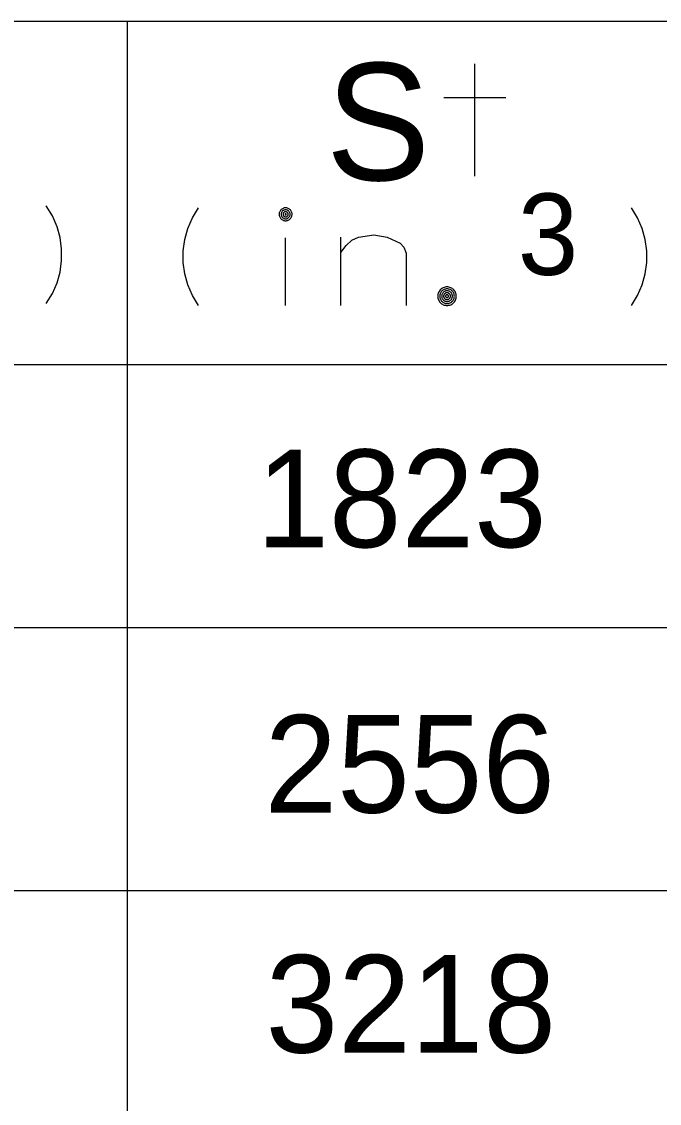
# Model space of a CAD drawing. Extents: x 635698 to 639877, y 296617 to 300175.
# Drawn here: x 639123.29 to 639142.89, y 299619.36 to 299652.6 of the extents above; entities that cross this region are included whole.
import ezdxf

# ---------------------------------------------------------------- set-up
doc = ezdxf.new("R2010")
doc.units = 0
for name, color, linetype in [('1', 7, 'Continuous'), ('2', 7, 'Continuous'), ('3', 7, 'Continuous')]:
    doc.layers.add(name, color=color, linetype=linetype)

msp = doc.modelspace()

# ---------------------------------------------------------------- linework, layer by layer
at = {"layer": '1'}
for p, q in [((639161.182, 299652.6), (639036.735, 299652.6)), ((639126.534, 299652.6), (639126.534, 299528.889)), ((639161.182, 299642.058), (639036.737, 299642.058)), ((639161.182, 299633.973), (639036.737, 299633.973)), ((639161.172, 299625.888), (639036.736, 299625.888)), ((639161.182, 299625.888), (639036.737, 299625.888))]:
    msp.add_line(p, q, dxfattribs=at)
at = {"layer": '2'}
for points in [[(639137.214, 299647.85), (639137.214, 299651.304)], [(639138.172, 299650.26), (639136.271, 299650.26)]]:
    msp.add_lwpolyline(points, dxfattribs=at)
at = {"layer": '3'}
for points in [[(639124.043, 299643.936), (639124.232, 299644.243), (639124.374, 299644.574), (639124.468, 299644.904), (639124.516, 299645.259), (639124.516, 299645.613), (639124.468, 299645.968), (639124.374, 299646.298), (639124.232, 299646.629), (639124.043, 299646.936)], [(639128.724, 299643.877), (639128.535, 299644.185), (639128.393, 299644.515), (639128.299, 299644.846), (639128.252, 299645.2), (639128.252, 299645.555), (639128.299, 299645.909), (639128.393, 299646.239), (639128.535, 299646.57), (639128.724, 299646.877)], [(639131.6, 299646.679), (639131.599, 299646.7), (639131.596, 299646.72), (639131.59, 299646.74), (639131.583, 299646.76), (639131.574, 299646.778), (639131.562, 299646.796), (639131.549, 299646.812), (639131.534, 299646.826), (639131.519, 299646.839), (639131.501, 299646.851), (639131.483, 299646.86), (639131.463, 299646.867), (639131.443, 299646.873), (639131.423, 299646.876), (639131.402, 299646.877), (639131.381, 299646.876), (639131.361, 299646.873), (639131.341, 299646.867), (639131.322, 299646.86), (639131.303, 299646.851), (639131.286, 299646.839), (639131.27, 299646.826), (639131.255, 299646.812), (639131.242, 299646.796), (639131.231, 299646.778), (639131.221, 299646.76), (639131.214, 299646.74), (639131.208, 299646.72), (639131.205, 299646.7), (639131.204, 299646.679), (639131.205, 299646.658), (639131.208, 299646.638), (639131.214, 299646.618), (639131.221, 299646.599), (639131.231, 299646.58), (639131.242, 299646.563), (639131.255, 299646.547), (639131.27, 299646.532), (639131.286, 299646.519), (639131.303, 299646.508), (639131.322, 299646.498), (639131.341, 299646.491), (639131.361, 299646.485), (639131.381, 299646.482), (639131.402, 299646.481), (639131.423, 299646.482), (639131.443, 299646.485), (639131.463, 299646.491), (639131.483, 299646.498), (639131.501, 299646.508), (639131.519, 299646.519), (639131.534, 299646.532), (639131.549, 299646.547), (639131.562, 299646.563), (639131.574, 299646.58), (639131.583, 299646.599), (639131.59, 299646.618), (639131.596, 299646.638), (639131.599, 299646.658), (639131.6, 299646.679)], [(639131.54, 299646.679), (639131.539, 299646.693), (639131.537, 299646.708), (639131.533, 299646.722), (639131.528, 299646.735), (639131.522, 299646.748), (639131.514, 299646.76), (639131.505, 299646.771), (639131.494, 299646.782), (639131.483, 299646.791), (639131.471, 299646.799), (639131.458, 299646.805), (639131.445, 299646.81), (639131.431, 299646.814), (639131.416, 299646.817), (639131.402, 299646.817), (639131.388, 299646.817), (639131.373, 299646.814), (639131.359, 299646.81), (639131.346, 299646.805), (639131.333, 299646.799), (639131.321, 299646.791), (639131.31, 299646.782), (639131.3, 299646.771), (639131.29, 299646.76), (639131.282, 299646.748), (639131.276, 299646.735), (639131.271, 299646.722), (639131.267, 299646.708), (639131.265, 299646.693), (639131.264, 299646.679), (639131.265, 299646.665), (639131.267, 299646.651), (639131.271, 299646.636), (639131.276, 299646.623), (639131.282, 299646.61), (639131.29, 299646.598), (639131.3, 299646.587), (639131.31, 299646.577), (639131.321, 299646.567), (639131.333, 299646.56), (639131.346, 299646.553), (639131.359, 299646.548), (639131.373, 299646.544), (639131.388, 299646.542), (639131.402, 299646.541), (639131.416, 299646.542), (639131.431, 299646.544), (639131.445, 299646.548), (639131.458, 299646.553), (639131.471, 299646.56), (639131.483, 299646.567), (639131.494, 299646.577), (639131.505, 299646.587), (639131.514, 299646.598), (639131.522, 299646.61), (639131.528, 299646.623), (639131.533, 299646.636), (639131.537, 299646.651), (639131.539, 299646.665), (639131.54, 299646.679)], [(639131.48, 299646.679), (639131.48, 299646.687), (639131.478, 299646.695), (639131.476, 299646.703), (639131.473, 299646.711), (639131.47, 299646.718), (639131.465, 299646.725), (639131.46, 299646.731), (639131.454, 299646.737), (639131.448, 299646.742), (639131.441, 299646.747), (639131.434, 299646.75), (639131.426, 299646.753), (639131.418, 299646.755), (639131.41, 299646.757), (639131.402, 299646.757), (639131.394, 299646.757), (639131.386, 299646.755), (639131.378, 299646.753), (639131.37, 299646.75), (639131.363, 299646.747), (639131.356, 299646.742), (639131.35, 299646.737), (639131.344, 299646.731), (639131.339, 299646.725), (639131.334, 299646.718), (639131.331, 299646.711), (639131.328, 299646.703), (639131.326, 299646.695), (639131.325, 299646.687), (639131.324, 299646.679), (639131.325, 299646.671), (639131.326, 299646.663), (639131.328, 299646.655), (639131.331, 299646.647), (639131.334, 299646.64), (639131.339, 299646.633), (639131.344, 299646.627), (639131.35, 299646.621), (639131.356, 299646.616), (639131.363, 299646.611), (639131.37, 299646.608), (639131.378, 299646.605), (639131.386, 299646.603), (639131.394, 299646.602), (639131.402, 299646.601), (639131.41, 299646.602), (639131.418, 299646.603), (639131.426, 299646.605), (639131.434, 299646.608), (639131.441, 299646.611), (639131.448, 299646.616), (639131.454, 299646.621), (639131.46, 299646.627), (639131.465, 299646.633), (639131.47, 299646.64), (639131.473, 299646.647), (639131.476, 299646.655), (639131.478, 299646.663), (639131.48, 299646.671), (639131.48, 299646.679)], [(639131.42, 299646.679), (639131.42, 299646.681), (639131.42, 299646.683), (639131.419, 299646.685), (639131.419, 299646.686), (639131.418, 299646.688), (639131.416, 299646.69), (639131.415, 299646.691), (639131.414, 299646.692), (639131.413, 299646.694), (639131.411, 299646.695), (639131.409, 299646.696), (639131.408, 299646.696), (639131.406, 299646.697), (639131.404, 299646.697), (639131.402, 299646.697), (639131.4, 299646.697), (639131.398, 299646.697), (639131.397, 299646.696), (639131.395, 299646.696), (639131.393, 299646.695), (639131.392, 299646.694), (639131.39, 299646.692), (639131.389, 299646.691), (639131.388, 299646.69), (639131.386, 299646.688), (639131.386, 299646.686), (639131.385, 299646.685), (639131.385, 299646.683), (639131.384, 299646.681), (639131.384, 299646.679), (639131.384, 299646.677), (639131.385, 299646.676), (639131.385, 299646.674), (639131.386, 299646.672), (639131.386, 299646.67), (639131.388, 299646.669), (639131.389, 299646.667), (639131.39, 299646.666), (639131.392, 299646.665), (639131.393, 299646.663), (639131.395, 299646.663), (639131.397, 299646.662), (639131.398, 299646.662), (639131.4, 299646.661), (639131.402, 299646.661), (639131.404, 299646.661), (639131.406, 299646.662), (639131.408, 299646.662), (639131.409, 299646.663), (639131.411, 299646.663), (639131.413, 299646.665), (639131.414, 299646.666), (639131.415, 299646.667), (639131.416, 299646.669), (639131.418, 299646.67), (639131.419, 299646.672), (639131.419, 299646.674), (639131.42, 299646.676), (639131.42, 299646.677), (639131.42, 299646.679)], [(639142.033, 299643.877), (639142.222, 299644.185), (639142.364, 299644.515), (639142.458, 299644.846), (639142.505, 299645.2), (639142.505, 299645.555), (639142.458, 299645.909), (639142.364, 299646.239), (639142.222, 299646.57), (639142.033, 299646.877)], [(639133.103, 299645.507), (639133.268, 299645.72), (639133.434, 299645.885), (639133.647, 299645.98), (639134.119, 299646.05), (639134.52, 299645.98), (639134.922, 299645.791), (639135.04, 299645.672), (639135.111, 299645.483), (639135.111, 299643.877)], [(639133.103, 299643.877), (639133.103, 299645.98)], [(639131.402, 299643.877), (639131.402, 299645.956)], [(639136.65, 299644.162), (639136.648, 299644.192), (639136.643, 299644.222), (639136.636, 299644.25), (639136.625, 299644.278), (639136.612, 299644.305), (639136.595, 299644.33), (639136.576, 299644.353), (639136.555, 299644.374), (639136.532, 299644.393), (639136.507, 299644.409), (639136.48, 299644.423), (639136.453, 299644.433), (639136.424, 299644.441), (639136.394, 299644.446), (639136.365, 299644.447), (639136.335, 299644.446), (639136.305, 299644.441), (639136.276, 299644.433), (639136.249, 299644.423), (639136.222, 299644.409), (639136.197, 299644.393), (639136.174, 299644.374), (639136.153, 299644.353), (639136.134, 299644.33), (639136.118, 299644.305), (639136.104, 299644.278), (639136.094, 299644.25), (639136.086, 299644.222), (639136.081, 299644.192), (639136.08, 299644.162), (639136.081, 299644.132), (639136.086, 299644.103), (639136.094, 299644.074), (639136.104, 299644.046), (639136.118, 299644.02), (639136.134, 299643.994), (639136.153, 299643.971), (639136.174, 299643.95), (639136.197, 299643.931), (639136.222, 299643.915), (639136.249, 299643.902), (639136.276, 299643.891), (639136.305, 299643.884), (639136.335, 299643.879), (639136.365, 299643.877), (639136.394, 299643.879), (639136.424, 299643.884), (639136.453, 299643.891), (639136.48, 299643.902), (639136.507, 299643.915), (639136.532, 299643.931), (639136.555, 299643.95), (639136.576, 299643.971), (639136.595, 299643.994), (639136.612, 299644.02), (639136.625, 299644.046), (639136.636, 299644.074), (639136.643, 299644.103), (639136.648, 299644.132), (639136.65, 299644.162)], [(639136.59, 299644.162), (639136.588, 299644.186), (639136.585, 299644.209), (639136.579, 299644.232), (639136.57, 299644.254), (639136.56, 299644.275), (639136.547, 299644.294), (639136.532, 299644.313), (639136.515, 299644.329), (639136.497, 299644.344), (639136.477, 299644.357), (639136.456, 299644.368), (639136.434, 299644.376), (639136.411, 299644.382), (639136.388, 299644.386), (639136.365, 299644.387), (639136.341, 299644.386), (639136.318, 299644.382), (639136.295, 299644.376), (639136.273, 299644.368), (639136.252, 299644.357), (639136.232, 299644.344), (639136.214, 299644.329), (639136.197, 299644.313), (639136.183, 299644.294), (639136.17, 299644.275), (639136.159, 299644.254), (639136.15, 299644.232), (639136.145, 299644.209), (639136.141, 299644.186), (639136.139, 299644.162), (639136.141, 299644.139), (639136.145, 299644.115), (639136.15, 299644.093), (639136.159, 299644.071), (639136.17, 299644.05), (639136.183, 299644.03), (639136.197, 299644.012), (639136.214, 299643.995), (639136.232, 299643.98), (639136.252, 299643.967), (639136.273, 299643.956), (639136.295, 299643.948), (639136.318, 299643.942), (639136.341, 299643.938), (639136.365, 299643.937), (639136.388, 299643.938), (639136.411, 299643.942), (639136.434, 299643.948), (639136.456, 299643.956), (639136.477, 299643.967), (639136.497, 299643.98), (639136.515, 299643.995), (639136.532, 299644.012), (639136.547, 299644.03), (639136.56, 299644.05), (639136.57, 299644.071), (639136.579, 299644.093), (639136.585, 299644.115), (639136.588, 299644.139), (639136.59, 299644.162)], [(639136.529, 299644.162), (639136.529, 299644.179), (639136.526, 299644.196), (639136.521, 299644.213), (639136.515, 299644.229), (639136.508, 299644.245), (639136.498, 299644.259), (639136.487, 299644.272), (639136.475, 299644.285), (639136.462, 299644.296), (639136.447, 299644.305), (639136.432, 299644.313), (639136.416, 299644.319), (639136.399, 299644.323), (639136.382, 299644.326), (639136.365, 299644.327), (639136.347, 299644.326), (639136.33, 299644.323), (639136.314, 299644.319), (639136.297, 299644.313), (639136.282, 299644.305), (639136.268, 299644.296), (639136.254, 299644.285), (639136.242, 299644.272), (639136.231, 299644.259), (639136.222, 299644.245), (639136.214, 299644.229), (639136.208, 299644.213), (639136.203, 299644.196), (639136.201, 299644.179), (639136.2, 299644.162), (639136.201, 299644.145), (639136.203, 299644.128), (639136.208, 299644.111), (639136.214, 299644.095), (639136.222, 299644.079), (639136.231, 299644.065), (639136.242, 299644.052), (639136.254, 299644.04), (639136.268, 299644.029), (639136.282, 299644.019), (639136.297, 299644.011), (639136.314, 299644.005), (639136.33, 299644.001), (639136.347, 299643.998), (639136.365, 299643.997), (639136.382, 299643.998), (639136.399, 299644.001), (639136.416, 299644.005), (639136.432, 299644.011), (639136.447, 299644.019), (639136.462, 299644.029), (639136.475, 299644.04), (639136.487, 299644.052), (639136.498, 299644.065), (639136.508, 299644.079), (639136.515, 299644.095), (639136.521, 299644.111), (639136.526, 299644.128), (639136.529, 299644.145), (639136.529, 299644.162)], [(639136.469, 299644.162), (639136.469, 299644.173), (639136.467, 299644.184), (639136.464, 299644.194), (639136.461, 299644.205), (639136.456, 299644.215), (639136.45, 299644.224), (639136.443, 299644.233), (639136.435, 299644.24), (639136.426, 299644.247), (639136.417, 299644.253), (639136.407, 299644.258), (639136.397, 299644.262), (639136.386, 299644.265), (639136.376, 299644.267), (639136.365, 299644.267), (639136.354, 299644.267), (639136.343, 299644.265), (639136.332, 299644.262), (639136.322, 299644.258), (639136.312, 299644.253), (639136.303, 299644.247), (639136.294, 299644.24), (639136.287, 299644.233), (639136.28, 299644.224), (639136.273, 299644.215), (639136.269, 299644.205), (639136.265, 299644.194), (639136.262, 299644.184), (639136.26, 299644.173), (639136.26, 299644.162), (639136.26, 299644.151), (639136.262, 299644.14), (639136.265, 299644.13), (639136.269, 299644.119), (639136.273, 299644.109), (639136.28, 299644.1), (639136.287, 299644.092), (639136.294, 299644.084), (639136.303, 299644.077), (639136.312, 299644.071), (639136.322, 299644.066), (639136.332, 299644.062), (639136.343, 299644.059), (639136.354, 299644.058), (639136.365, 299644.057), (639136.376, 299644.058), (639136.386, 299644.059), (639136.397, 299644.062), (639136.407, 299644.066), (639136.417, 299644.071), (639136.426, 299644.077), (639136.435, 299644.084), (639136.443, 299644.092), (639136.45, 299644.1), (639136.456, 299644.109), (639136.461, 299644.119), (639136.464, 299644.13), (639136.467, 299644.14), (639136.469, 299644.151), (639136.469, 299644.162)], [(639136.41, 299644.162), (639136.409, 299644.167), (639136.409, 299644.171), (639136.408, 299644.176), (639136.406, 299644.181), (639136.404, 299644.185), (639136.401, 299644.189), (639136.398, 299644.192), (639136.395, 299644.196), (639136.391, 299644.198), (639136.387, 299644.201), (639136.383, 299644.203), (639136.379, 299644.205), (639136.374, 299644.206), (639136.369, 299644.207), (639136.365, 299644.207), (639136.36, 299644.207), (639136.355, 299644.206), (639136.351, 299644.205), (639136.346, 299644.203), (639136.342, 299644.201), (639136.338, 299644.198), (639136.335, 299644.196), (639136.331, 299644.192), (639136.328, 299644.189), (639136.326, 299644.185), (639136.323, 299644.181), (639136.322, 299644.176), (639136.321, 299644.171), (639136.32, 299644.167), (639136.32, 299644.162), (639136.32, 299644.157), (639136.321, 299644.153), (639136.322, 299644.148), (639136.323, 299644.144), (639136.326, 299644.14), (639136.328, 299644.136), (639136.331, 299644.132), (639136.335, 299644.129), (639136.338, 299644.126), (639136.342, 299644.123), (639136.346, 299644.121), (639136.351, 299644.119), (639136.355, 299644.118), (639136.36, 299644.118), (639136.365, 299644.117), (639136.369, 299644.118), (639136.374, 299644.118), (639136.379, 299644.119), (639136.383, 299644.121), (639136.387, 299644.123), (639136.391, 299644.126), (639136.395, 299644.129), (639136.398, 299644.132), (639136.401, 299644.136), (639136.404, 299644.14), (639136.406, 299644.144), (639136.408, 299644.148), (639136.409, 299644.153), (639136.409, 299644.157), (639136.41, 299644.162)]]:
    msp.add_lwpolyline(points, dxfattribs=at)

# ---------------------------------------------------------------- texts
at = {"layer": '2'}
msp.add_text('S', height=3.6, dxfattribs=at).set_placement((639132.638, 299647.727))
msp.add_text('3218', height=3.0008, rotation=360, dxfattribs=at).set_placement((639130.788, 299620.916))
at = {"layer": '3'}
for s, height, p in [('3', 2.5, (639138.54, 299644.818)), ('1823', 3.001, (639130.501, 299636.448)), ('2556', 3.001, (639130.755, 299628.29))]:
    msp.add_text(s, height=height, dxfattribs=at).set_placement(p)

doc.saveas('drawing.dxf')
